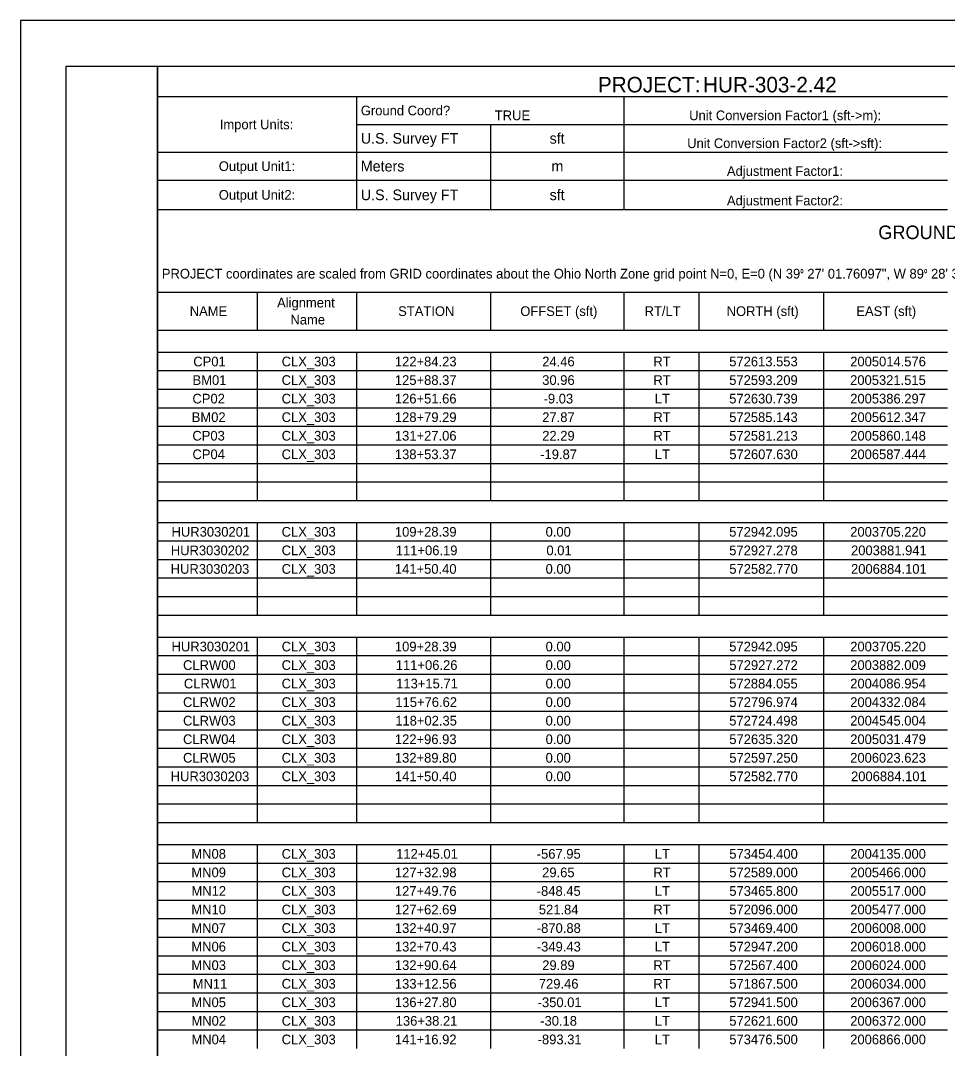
# Model space of a CAD drawing. Extents: x 0 to 34, y 0 to 22.
# Drawn here: x 0 to 10.14, y 10.76 to 22 of the extents above; entities that cross this region are included whole.
import ezdxf

# ---------------------------------------------------------------- set-up
doc = ezdxf.new("R2010")
doc.units = 0
for name, color, linetype in [('SH_Border', 7, 'Continuous'), ('SH_Cut_Line', 7, 'Continuous'), ('SH_Text', 7, 'Continuous')]:
    doc.layers.add(name, color=color, linetype=linetype)

msp = doc.modelspace()

# ---------------------------------------------------------------- linework, layer by layer
at = {"layer": 'SH_Border'}
for points in [[(0.5, 21.5), (1.5, 21.5), (1.5, 0.5), (0.5, 0.5)], [(1.5, 21.5), (33.5, 21.5), (33.5, 0.5), (1.5, 0.5)]]:
    msp.add_lwpolyline(points, close=True, dxfattribs=at)
at = {"layer": 'SH_Cut_Line'}
msp.add_lwpolyline([(0, 0), (34, 0), (34, 22), (0, 22)], close=True, dxfattribs=at)
at = {"layer": 'SH_Text'}
for p, q in [((1.5, 21.168), (10.142, 21.168)), ((1.5, 21.168), (1.5, 19.028)), ((3.677, 21.168), (3.677, 19.932)), ((6.6, 21.168), (6.6, 19.932)), ((3.677, 20.864), (10.142, 20.864)), ((5.143, 20.864), (5.143, 19.932)), ((1.5, 20.559), (6.6, 20.559)), ((6.6, 20.559), (10.142, 20.559)), ((1.5, 20.255), (10.142, 20.255)), ((1.5, 19.932), (6.6, 19.932)), ((6.6, 19.932), (10.142, 19.932)), ((1.5, 19.028), (10.142, 19.028)), ((1.5, 19.028), (1.5, 17.359)), ((2.588, 19.028), (2.588, 18.613)), ((3.677, 19.028), (3.677, 18.613)), ((5.143, 19.028), (5.143, 18.613)), ((6.6, 19.028), (6.6, 18.613)), ((7.421, 19.028), (7.421, 18.613)), ((8.786, 19.028), (8.786, 18.613)), ((1.5, 18.613), (10.142, 18.613)), ((1.5, 18.373), (10.142, 18.373)), ((2.588, 18.373), (2.588, 17.359)), ((3.677, 18.373), (3.677, 17.359)), ((5.143, 18.373), (5.143, 17.359)), ((6.6, 18.373), (6.6, 17.359)), ((7.421, 18.373), (7.421, 17.359)), ((8.786, 18.373), (8.786, 17.359)), ((1.5, 18.171), (10.142, 18.171)), ((1.5, 17.968), (10.142, 17.968)), ((1.5, 17.765), (10.142, 17.765)), ((1.5, 17.562), (10.142, 17.562)), ((1.5, 17.359), (10.142, 17.359)), ((1.5, 17.359), (1.5, 17.156)), ((2.588, 17.359), (2.588, 17.156)), ((3.677, 17.359), (3.677, 17.156)), ((5.143, 17.359), (5.143, 17.156)), ((6.6, 17.359), (6.6, 17.156)), ((7.421, 17.359), (7.421, 17.156)), ((8.786, 17.359), (8.786, 17.156)), ((1.5, 17.156), (10.142, 17.156)), ((1.5, 17.156), (1.5, 16.953)), ((2.588, 17.156), (2.588, 16.953)), ((3.677, 17.156), (3.677, 16.953)), ((5.143, 17.156), (5.143, 16.953)), ((6.6, 17.156), (6.6, 16.953)), ((7.421, 17.156), (7.421, 16.953)), ((8.786, 17.156), (8.786, 16.953)), ((1.5, 16.953), (10.142, 16.953)), ((1.5, 16.953), (1.5, 16.51)), ((2.588, 16.953), (2.588, 16.75)), ((3.677, 16.953), (3.677, 16.75)), ((5.143, 16.953), (5.143, 16.75)), ((6.6, 16.953), (6.6, 16.75)), ((7.421, 16.953), (7.421, 16.75)), ((8.786, 16.953), (8.786, 16.75)), ((1.5, 16.75), (10.142, 16.75)), ((1.5, 16.51), (10.142, 16.51)), ((1.5, 16.51), (1.5, 16.308)), ((2.588, 16.51), (2.588, 16.308)), ((3.677, 16.51), (3.677, 16.308)), ((5.143, 16.51), (5.143, 16.308)), ((6.6, 16.51), (6.6, 16.308)), ((7.421, 16.51), (7.421, 16.308)), ((8.786, 16.51), (8.786, 16.308)), ((1.5, 16.308), (10.142, 16.308)), ((1.5, 16.308), (1.5, 13.227)), ((2.588, 16.308), (2.588, 15.496)), ((3.677, 16.308), (3.677, 15.496)), ((5.143, 16.308), (5.143, 15.496)), ((6.6, 16.308), (6.6, 15.496)), ((7.421, 16.308), (7.421, 15.496)), ((8.786, 16.308), (8.786, 15.496)), ((1.5, 16.105), (10.142, 16.105)), ((1.5, 15.902), (10.142, 15.902)), ((1.5, 15.699), (10.142, 15.699)), ((1.5, 15.496), (10.142, 15.496)), ((1.5, 15.256), (10.142, 15.256)), ((2.588, 15.256), (2.588, 13.227)), ((3.677, 15.256), (3.677, 13.227)), ((5.143, 15.256), (5.143, 13.227)), ((6.6, 15.256), (6.6, 13.227)), ((7.421, 15.256), (7.421, 13.227)), ((8.786, 15.256), (8.786, 13.227)), ((1.5, 15.053), (10.142, 15.053)), ((1.5, 14.85), (10.142, 14.85)), ((1.5, 14.647), (10.142, 14.647)), ((1.5, 14.445), (10.142, 14.445)), ((1.5, 14.242), (10.142, 14.242)), ((1.5, 14.039), (10.142, 14.039)), ((1.5, 13.836), (10.142, 13.836)), ((1.5, 13.633), (10.142, 13.633)), ((1.5, 13.43), (10.142, 13.43)), ((1.5, 13.227), (10.142, 13.227)), ((1.5, 13.227), (1.5, 12.987)), ((1.5, 12.987), (10.142, 12.987)), ((1.5, 12.987), (1.5, 12.784)), ((2.588, 12.987), (2.588, 12.784)), ((3.677, 12.987), (3.677, 12.784)), ((5.143, 12.987), (5.143, 12.784)), ((6.6, 12.987), (6.6, 12.784)), ((7.421, 12.987), (7.421, 12.784)), ((8.786, 12.987), (8.786, 12.784)), ((1.5, 12.784), (10.142, 12.784)), ((1.5, 12.784), (1.5, 12.581)), ((2.588, 12.784), (2.588, 12.581)), ((3.677, 12.784), (3.677, 12.581)), ((5.143, 12.784), (5.143, 12.581)), ((6.6, 12.784), (6.6, 12.581)), ((7.421, 12.784), (7.421, 12.581)), ((8.786, 12.784), (8.786, 12.581)), ((1.5, 12.581), (10.142, 12.581)), ((1.5, 12.581), (1.5, 12.379)), ((2.588, 12.581), (2.588, 12.379)), ((3.677, 12.581), (3.677, 12.379)), ((5.143, 12.581), (5.143, 12.379)), ((6.6, 12.581), (6.6, 12.379)), ((7.421, 12.581), (7.421, 12.379)), ((8.786, 12.581), (8.786, 12.379)), ((1.5, 12.379), (10.142, 12.379)), ((1.5, 12.379), (1.5, 11.973)), ((2.588, 12.379), (2.588, 11.973)), ((3.677, 12.379), (3.677, 11.973)), ((5.143, 12.379), (5.143, 11.973)), ((6.6, 12.379), (6.6, 11.973)), ((7.421, 12.379), (7.421, 11.973)), ((8.786, 12.379), (8.786, 11.973)), ((1.5, 12.176), (10.142, 12.176)), ((1.5, 11.973), (10.142, 11.973)), ((1.5, 11.973), (1.5, 11.77)), ((2.588, 11.973), (2.588, 11.77)), ((3.677, 11.973), (3.677, 11.77)), ((5.143, 11.973), (5.143, 11.77)), ((6.6, 11.973), (6.6, 11.77)), ((7.421, 11.973), (7.421, 11.77)), ((8.786, 11.973), (8.786, 11.77)), ((1.5, 11.77), (10.142, 11.77)), ((1.5, 11.77), (1.5, 11.567)), ((2.588, 11.77), (2.588, 11.567)), ((3.677, 11.77), (3.677, 11.567)), ((5.143, 11.77), (5.143, 11.567)), ((6.6, 11.77), (6.6, 11.567)), ((7.421, 11.77), (7.421, 11.567)), ((8.786, 11.77), (8.786, 11.567)), ((1.5, 11.567), (10.142, 11.567)), ((1.5, 11.567), (1.5, 11.364)), ((2.588, 11.567), (2.588, 11.364)), ((3.677, 11.567), (3.677, 11.364)), ((5.143, 11.567), (5.143, 11.364)), ((6.6, 11.567), (6.6, 11.364)), ((7.421, 11.567), (7.421, 11.364)), ((8.786, 11.567), (8.786, 11.364)), ((1.5, 11.364), (10.142, 11.364)), ((1.5, 11.364), (1.5, 10.958)), ((2.588, 11.364), (2.588, 10.958)), ((3.677, 11.364), (3.677, 10.958)), ((5.143, 11.364), (5.143, 10.958)), ((6.6, 11.364), (6.6, 10.958)), ((7.421, 11.364), (7.421, 10.958)), ((8.786, 11.364), (8.786, 10.958)), ((1.5, 11.161), (10.142, 11.161)), ((1.5, 10.958), (10.142, 10.958)), ((1.5, 10.958), (1.5, 10.755)), ((2.588, 10.958), (2.588, 10.755)), ((3.677, 10.958), (3.677, 10.755)), ((5.143, 10.958), (5.143, 10.755)), ((6.6, 10.958), (6.6, 10.755)), ((7.421, 10.958), (7.421, 10.755)), ((8.786, 10.958), (8.786, 10.755))]:
    msp.add_line(p, q, dxfattribs=at)

# ---------------------------------------------------------------- texts
for s, height, p in [('PROJECT:', 0.1697, (6.317, 21.214)), ('HUR-303-2.42', 0.1697, (7.467, 21.214)), ('Ground Coord?', 0.10606, (3.723, 20.963)), ('Import Units:', 0.10606, (2.18, 20.811)), ('TRUE', 0.1061, (5.189, 20.91)), ('Unit Conversion Factor1 (sft->m):', 0.10606, (7.316, 20.91)), ('U.S. Survey FT', 0.11667, (3.723, 20.653)), ('sft', 0.1167, (5.789, 20.653)), ('Unit Conversion Factor2 (sft->sft):', 0.10606, (7.294, 20.605)), ('Output Unit1:', 0.10606, (2.169, 20.354)), ('Meters', 0.1167, (3.723, 20.349)), ('m', 0.117, (5.809, 20.349)), ('Adjustment Factor1:', 0.10606, (7.729, 20.301)), ('Output Unit2:', 0.10606, (2.169, 20.04)), ('U.S. Survey FT', 0.11667, (3.723, 20.035)), ('sft', 0.1167, (5.789, 20.035)), ('Adjustment Factor2:', 0.10606, (7.729, 19.978)), ('GROUND COORDINATES - U.S. Survey FT', 0.14849, (9.385, 19.609)), ('PROJECT coordinates are scaled from GRID coordinates about the Ohio North Zone grid point N=0, E=0 (N 39⁰ 27\' 01.76097", W 89⁰ 28\' 32.98476")', 0.106063, (1.546, 19.178)), ('Alignment ', 0.1061, (2.807, 18.861)), ('NAME', 0.1061, (1.851, 18.768)), ('Name', 0.1061, (2.953, 18.675)), ('STATION', 0.1061, (4.132, 18.768)), ('OFFSET (sft)', 0.10606, (5.468, 18.768)), ('RT/LT', 0.1061, (6.828, 18.768)), ('NORTH (sft)', 0.10606, (7.726, 18.768)), ('EAST (sft)', 0.1061, (9.145, 18.768)), ('CP01', 0.1061, (1.89, 18.217)), ('CLX_303', 0.1061, (2.857, 18.217)), ('122+84.23', 0.1061, (4.096, 18.217)), ('24.46', 0.1061, (5.708, 18.217)), ('RT', 0.1061, (6.924, 18.217)), ('572613.553', 0.1061, (7.754, 18.217)), ('2005014.576', 0.10606, (9.078, 18.217)), ('BM01', 0.1061, (1.882, 18.014)), ('CLX_303', 0.1061, (2.857, 18.014)), ('125+88.37', 0.1061, (4.096, 18.014)), ('30.96', 0.1061, (5.708, 18.014)), ('RT', 0.1061, (6.924, 18.014)), ('572593.209', 0.1061, (7.754, 18.014)), ('2005321.515', 0.10606, (9.077, 18.014)), ('CP02', 0.1061, (1.881, 17.811)), ('CLX_303', 0.1061, (2.857, 17.811)), ('126+51.66', 0.1061, (4.096, 17.811)), ('-9.03', 0.1061, (5.723, 17.811)), ('LT', 0.1061, (6.939, 17.811)), ('572630.739', 0.1061, (7.754, 17.811)), ('2005386.297', 0.10606, (9.078, 17.811)), ('BM02', 0.1061, (1.873, 17.608)), ('CLX_303', 0.1061, (2.857, 17.608)), ('128+79.29', 0.1061, (4.096, 17.608)), ('27.87', 0.1061, (5.708, 17.608)), ('RT', 0.1061, (6.924, 17.608)), ('572585.143', 0.1061, (7.754, 17.608)), ('2005612.347', 0.10606, (9.078, 17.608)), ('CP03', 0.1061, (1.88, 17.405)), ('CLX_303', 0.1061, (2.857, 17.405)), ('131+27.06', 0.1061, (4.096, 17.405)), ('22.29', 0.1061, (5.708, 17.405)), ('RT', 0.1061, (6.924, 17.405)), ('572581.213', 0.1061, (7.754, 17.405)), ('2005860.148', 0.10606, (9.078, 17.405)), ('CP04', 0.1061, (1.881, 17.202)), ('CLX_303', 0.1061, (2.857, 17.202)), ('138+53.37', 0.1061, (4.096, 17.202)), ('-19.87', 0.1061, (5.686, 17.202)), ('LT', 0.1061, (6.939, 17.202)), ('572607.630', 0.1061, (7.755, 17.202)), ('2006587.444', 0.10606, (9.078, 17.202)), ('HUR3030201', 0.1061, (1.652, 16.354)), ('CLX_303', 0.1061, (2.857, 16.354)), ('109+28.39', 0.1061, (4.096, 16.354)), ('0.00', 0.1061, (5.745, 16.354)), ('572942.095', 0.1061, (7.754, 16.354)), ('2003705.220', 0.10606, (9.078, 16.354)), ('HUR3030202', 0.1061, (1.644, 16.151)), ('CLX_303', 0.1061, (2.857, 16.151)), ('111+06.19', 0.1061, (4.106, 16.151)), ('0.01', 0.1061, (5.754, 16.151)), ('572927.278', 0.1061, (7.754, 16.151)), ('2003881.941', 0.10606, (9.087, 16.151)), ('HUR3030203', 0.1061, (1.643, 15.948)), ('CLX_303', 0.1061, (2.857, 15.948)), ('141+50.40', 0.1061, (4.096, 15.948)), ('0.00', 0.1061, (5.745, 15.948)), ('572582.770', 0.1061, (7.755, 15.948)), ('2006884.101', 0.10606, (9.087, 15.948)), ('HUR3030201', 0.1061, (1.652, 15.099)), ('CLX_303', 0.1061, (2.857, 15.099)), ('109+28.39', 0.1061, (4.096, 15.099)), ('0.00', 0.1061, (5.745, 15.099)), ('572942.095', 0.1061, (7.754, 15.099)), ('2003705.220', 0.10606, (9.078, 15.099)), ('CLRW00', 0.1061, (1.778, 14.896)), ('CLX_303', 0.1061, (2.857, 14.896)), ('111+06.26', 0.1061, (4.106, 14.896)), ('0.00', 0.1061, (5.745, 14.896)), ('572927.272', 0.1061, (7.755, 14.896)), ('2003882.009', 0.10606, (9.078, 14.896)), ('CLRW01', 0.1061, (1.787, 14.694)), ('CLX_303', 0.1061, (2.857, 14.694)), ('113+15.71', 0.1061, (4.11, 14.694)), ('0.00', 0.1061, (5.745, 14.694)), ('572884.055', 0.1061, (7.754, 14.694)), ('2004086.954', 0.10606, (9.078, 14.694)), ('CLRW02', 0.1061, (1.778, 14.491)), ('CLX_303', 0.1061, (2.857, 14.491)), ('115+76.62', 0.1061, (4.101, 14.491)), ('0.00', 0.1061, (5.745, 14.491)), ('572796.974', 0.1061, (7.755, 14.491)), ('2004332.084', 0.10606, (9.078, 14.491)), ('CLRW03', 0.1061, (1.778, 14.288)), ('CLX_303', 0.1061, (2.857, 14.288)), ('118+02.35', 0.1061, (4.1, 14.288)), ('0.00', 0.1061, (5.745, 14.288)), ('572724.498', 0.1061, (7.754, 14.288)), ('2004545.004', 0.10606, (9.078, 14.288)), ('CLRW04', 0.1061, (1.778, 14.085)), ('CLX_303', 0.1061, (2.857, 14.085)), ('122+96.93', 0.1061, (4.096, 14.085)), ('0.00', 0.1061, (5.745, 14.085)), ('572635.320', 0.1061, (7.755, 14.085)), ('2005031.479', 0.10606, (9.078, 14.085)), ('CLRW05', 0.1061, (1.778, 13.882)), ('CLX_303', 0.1061, (2.857, 13.882)), ('132+89.80', 0.1061, (4.096, 13.882)), ('0.00', 0.1061, (5.745, 13.882)), ('572597.250', 0.1061, (7.755, 13.882)), ('2006023.623', 0.10606, (9.078, 13.882)), ('HUR3030203', 0.1061, (1.643, 13.679)), ('CLX_303', 0.1061, (2.857, 13.679)), ('141+50.40', 0.1061, (4.096, 13.679)), ('0.00', 0.1061, (5.745, 13.679)), ('572582.770', 0.1061, (7.755, 13.679)), ('2006884.101', 0.10606, (9.087, 13.679)), ('MN08', 0.1061, (1.869, 12.831)), ('CLX_303', 0.1061, (2.857, 12.831)), ('112+45.01', 0.1061, (4.11, 12.831)), ('-567.95', 0.1061, (5.648, 12.831)), ('LT', 0.1061, (6.939, 12.831)), ('573454.400', 0.1061, (7.755, 12.831)), ('2004135.000', 0.10606, (9.078, 12.831)), ('MN09', 0.1061, (1.869, 12.628)), ('CLX_303', 0.1061, (2.857, 12.628)), ('127+32.98', 0.1061, (4.096, 12.628)), ('29.65', 0.1061, (5.707, 12.628)), ('RT', 0.1061, (6.924, 12.628)), ('572589.000', 0.1061, (7.755, 12.628)), ('2005466.000', 0.10606, (9.078, 12.628)), ('MN12', 0.1061, (1.87, 12.425)), ('CLX_303', 0.1061, (2.857, 12.425)), ('127+49.76', 0.1061, (4.096, 12.425)), ('-848.45', 0.1061, (5.648, 12.425)), ('LT', 0.1061, (6.939, 12.425)), ('573465.800', 0.1061, (7.755, 12.425)), ('2005517.000', 0.10606, (9.078, 12.425)), ('MN10', 0.1061, (1.869, 12.222)), ('CLX_303', 0.1061, (2.857, 12.222)), ('127+62.69', 0.1061, (4.096, 12.222)), ('521.84', 0.1061, (5.671, 12.222)), ('RT', 0.1061, (6.924, 12.222)), ('572096.000', 0.1061, (7.755, 12.222)), ('2005477.000', 0.10606, (9.078, 12.222)), ('MN07', 0.1061, (1.869, 12.019)), ('CLX_303', 0.1061, (2.857, 12.019)), ('132+40.97', 0.1061, (4.096, 12.019)), ('-870.88', 0.1061, (5.649, 12.019)), ('LT', 0.1061, (6.939, 12.019)), ('573469.400', 0.1061, (7.755, 12.019)), ('2006008.000', 0.10606, (9.078, 12.019)), ('MN06', 0.1061, (1.869, 11.816)), ('CLX_303', 0.1061, (2.857, 11.816)), ('132+70.43', 0.1061, (4.096, 11.816)), ('-349.43', 0.1061, (5.649, 11.816)), ('LT', 0.1061, (6.939, 11.816)), ('572947.200', 0.1061, (7.755, 11.816)), ('2006018.000', 0.10606, (9.078, 11.816)), ('MN03', 0.1061, (1.869, 11.613)), ('CLX_303', 0.1061, (2.857, 11.613)), ('132+90.64', 0.1061, (4.096, 11.613)), ('29.89', 0.1061, (5.708, 11.613)), ('RT', 0.1061, (6.924, 11.613)), ('572567.400', 0.1061, (7.755, 11.613)), ('2006024.000', 0.10606, (9.078, 11.613)), ('MN11', 0.1061, (1.884, 11.41)), ('CLX_303', 0.1061, (2.857, 11.41)), ('133+12.56', 0.1061, (4.096, 11.41)), ('729.46', 0.1061, (5.671, 11.41)), ('RT', 0.1061, (6.924, 11.41)), ('571867.500', 0.1061, (7.755, 11.41)), ('2006034.000', 0.10606, (9.078, 11.41)), ('MN05', 0.1061, (1.869, 11.207)), ('CLX_303', 0.1061, (2.857, 11.207)), ('136+27.80', 0.1061, (4.096, 11.207)), ('-350.01', 0.1061, (5.658, 11.207)), ('LT', 0.1061, (6.939, 11.207)), ('572941.500', 0.1061, (7.755, 11.207)), ('2006367.000', 0.10606, (9.078, 11.207)), ('MN02', 0.1061, (1.87, 11.004)), ('CLX_303', 0.1061, (2.857, 11.004)), ('136+38.21', 0.1061, (4.105, 11.004)), ('-30.18', 0.1061, (5.686, 11.004)), ('LT', 0.1061, (6.939, 11.004)), ('572621.600', 0.1061, (7.755, 11.004)), ('2006372.000', 0.10606, (9.078, 11.004)), ('MN04', 0.1061, (1.87, 10.801)), ('CLX_303', 0.1061, (2.857, 10.801)), ('141+16.92', 0.1061, (4.096, 10.801)), ('-893.31', 0.1061, (5.658, 10.801)), ('LT', 0.1061, (6.939, 10.801)), ('573476.500', 0.1061, (7.755, 10.801)), ('2006866.000', 0.10606, (9.078, 10.801))]:
    msp.add_text(s, height=height, dxfattribs=at).set_placement(p)

doc.saveas('drawing.dxf')
